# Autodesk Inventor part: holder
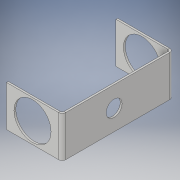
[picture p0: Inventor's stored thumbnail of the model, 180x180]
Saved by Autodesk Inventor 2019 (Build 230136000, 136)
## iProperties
Created: 2020-02
Part Number: holder
Material: Generic
Document SubType Name: Sheet Metal
Designer: ash
Density: 1 g/cm^3
Sheet Metal Rule: Default_mm
Appearance: Default
Author: ash
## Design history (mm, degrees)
node "Face1"
  sketch "Sketch1"
    geometry: L1 (0, 0)-(11, 0); L2 (11, 0)-(11, -30); L3 (11, -30)-(0, -30); L4 (0, -30)-(0, 0); C1 r 2.15 at (5.5, -15)
    constraints: 8 end point, 2 parallel, 1 centre point, 1 horizontal, 1 perpendicular
    dimensions: "d0" = 11 distance of L2.end L3.end; "d1" = 30 distance of L1.end L2.end; "d24" = 4.3 diameter of C1; "d25" = 5.5 distance from line of L4 C1.centre; "d26" = 15 distance from line of L3 C1.centre
node "Flange1"
sketch "Sketch3"
  geometry: L1 (0, 0)-(-14, 0) reference; L2 (0, 11)-(0, 0) reference; 2 further points
  dimensions: "d22" = 5.5 distance from line of L1 point (-7, 5.5); "d23" = 7 distance from line of L2 point (-7, 5.5)
hole "Hole1" sketch "Sketch3" diameter "d15" = 10; stored, may be unused: countersink angle "d19" = 90 deg, drill point angle "d21" = 118 deg; dims "d16" = 6, "d17" = 4, "d18" = 2, "d20" = 0.5 (= Thickness)
sketch "Sketch4"
  geometry: L1 (29, 0)-(1, 0) reference; L2 (29, 0)-(29, 11) reference; 2 further points
  dimensions: "d27" = 5.5 distance from line of L1 point (14, 5.5); "d28" = 15 distance from line of L2 point (14, 5.5)
hole "Hole2" sketch "Sketch4" at (14, 5.5) diameter "d29" = 4.3; stored, may be unused: countersink angle "d33" = 90 deg, drill point angle "d35" = 118 deg; dims "d30" = 6, "d31" = 4, "d32" = 2, "d34" = 0.5 (= Thickness)
body "Solid2"
face "Plate1" dims "d4" = 0.5 (= Thickness)
sketch "Sketch2"
  geometry: L1 through (0, 5.5) direction (0, -1); L2 through (7.5, 0) direction (1, 0); L3 (15, 0)-(15, 11); L4 (15, 11)-(0, 11)
  constraints: 6 end point, 1 horizontal, 1 perpendicular, 1 vertical
face "Plate2" dims "d4" = 0.5 (= Thickness), "d5" = 0.5 (= BendReliefWidth), "d6" = 0.25 (= BendReliefDepth), "d7" = 1 (= MinimumRemnant), "d8" = 0.5 (= TransitionRadius), "d9" = 15, "d10" = 90 deg, "d11" = 0.5 (= BendRadius), "d12" = 2 (= CornerReliefSize), "d13" = 0.5 (= GapSize), "d14" = 0.5 (= JacobiRadiusSize), "SeamGap" = 0.01
bend "Bend1" dims "d4" = 0.5 (= Thickness), "d5" = 0.5 (= BendReliefWidth), "d6" = 0.25 (= BendReliefDepth), "d7" = 1 (= MinimumRemnant), "d8" = 0.5 (= TransitionRadius), "d9" = 15, "d10" = 90 deg, "d11" = 0.5 (= BendRadius), "SeamGap" = 0.01
feature "Corner1" dims "d9" = 15, "d10" = 90 deg, "d12" = 2 (= CornerReliefSize), "d13" = 0.5 (= GapSize), "d14" = 0.5 (= JacobiRadiusSize)
other parameters: "Thickness" = 0.5, "BendRadius" = 0.5 (= Thickness), "BendReliefWidth" = 0.5 (= Thickness), "BendReliefDepth" = 0.25 (= 0.5 x Thickness), "CornerReliefSize" = 2 (= 4 x Thickness), "MinimumRemnant" = 1 (= 2 x Thickness), "TransitionRadius" = 0.5 (= BendRadius), "JacobiRadiusSize" = 0.5 (= BendRadius), "GapSize" = 0.5 (= Thickness)
